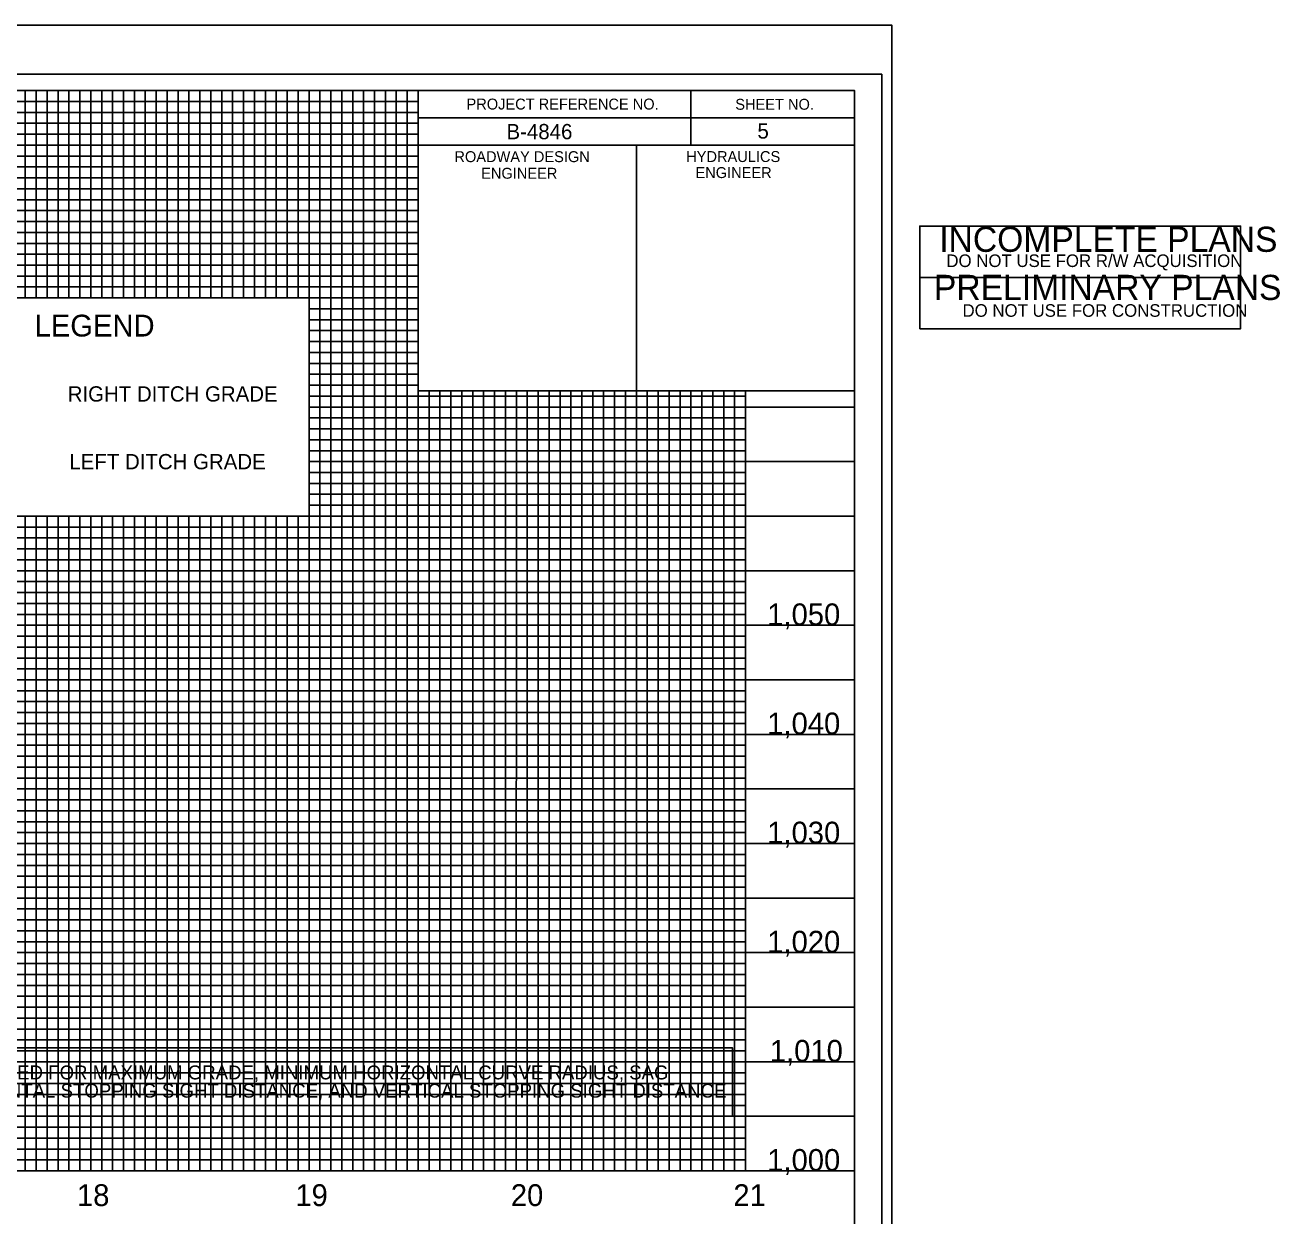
# Model space of a CAD drawing. Extents: x 1427348 to 1429459, y 856278 to 857378.
# Drawn here: x 1428884 to 1429459, y 856832 to 857378 of the extents above; entities that cross this region are included whole.
import ezdxf

# ---------------------------------------------------------------- set-up
doc = ezdxf.new("R2010")
doc.units = 0
for name, color, linetype in [('Exist Vertical Profile Horizontal Axis Label Major', 7, 'Continuous'), ('Exist Vertical Profile Vertical Axis Label', 7, 'Continuous'), ('Prop Grid Mask', 7, 'Continuous'), ('Prop Vertical Profile Curve Label', 7, 'Continuous'), ('Prop Vertical Profile Ditch Grade Left Label', 7, 'Continuous'), ('Prop Vertical Profile Ditch Grade Right Label', 7, 'Continuous'), ('Sheet Cutting Line CELL', 7, 'Continuous'), ('Sheet Data Field CELL', 7, 'Continuous'), ('Sheet DOT Grid CELL', 7, 'Continuous'), ('Sheet Layout Profile Border Port 1', 7, 'Continuous'), ('Sheet Plot Border Inside CELL', 7, 'Continuous'), ('Sheet Plot Border Outside CELL', 7, 'Continuous'), ('Sheet Profile CELL', 7, 'Continuous'), ('Sheet Profile Grid Major CELL', 7, 'Continuous'), ('Sheet Profile Grid Middle CELL', 7, 'Continuous'), ('Sheet Profile Grid Minor CELL', 7, 'Continuous'), ('Sheet Sticker Incomplete CELL', 7, 'Continuous'), ('Sheet Sticker Preliminary CELL', 7, 'Continuous')]:
    doc.layers.add(name, color=color, linetype=linetype)

msp = doc.modelspace()

# ---------------------------------------------------------------- linework, layer by layer
at = {"layer": 'Prop Grid Mask'}
msp.add_lwpolyline([(1428746.32, 856908.99), (1429208.01, 856908.99), (1429208.01, 856877.58), (1428746.32, 856877.58)], close=True, dxfattribs=at)
at = {"layer": 'Sheet Cutting Line CELL'}
msp.add_line((1429280.99, 857377.58), (1427596.99, 857377.58), dxfattribs=at)
at = {"layer": 'Sheet DOT Grid CELL'}
for p, q in [((1428913.99, 857252.58), (1428913.99, 857347.58)), ((1428963.99, 857252.58), (1428963.99, 857347.58)), ((1429013.99, 856852.58), (1429013.99, 857347.58)), ((1429063.94, 857302.58), (1428179.55, 857302.58)), ((1429063.94, 857252.58), (1428388.99, 857252.58)), ((1429063.99, 856852.58), (1429063.99, 857215.03)), ((1429163.99, 856852.58), (1429163.99, 857215.03)), ((1429113.99, 856852.58), (1429113.99, 857210.03)), ((1429213.99, 856852.58), (1429213.99, 857210.03)), ((1429263.99, 857202.58), (1429013.99, 857202.58)), ((1429263.99, 857152.58), (1428179.55, 857152.58)), ((1428913.99, 856852.58), (1428913.99, 857152.58)), ((1428963.99, 856852.58), (1428963.99, 857152.58)), ((1429263.99, 857102.58), (1428179.55, 857102.58)), ((1429263.99, 857052.58), (1428712.85, 857052.58)), ((1429263.99, 857002.58), (1428427.25, 857002.58)), ((1429263.99, 856952.58), (1427763.99, 856952.58)), ((1429263.99, 856902.58), (1427763.99, 856902.58))]:
    msp.add_line(p, q, dxfattribs=at)
at = {"layer": 'Sheet Layout Profile Border Port 1'}
msp.add_lwpolyline([(1427813.99, 857347.58), (1427813.99, 856852.58), (1429213.99, 856852.58), (1429213.99, 857210.03), (1429063.94, 857210.03), (1429063.94, 857347.58)], close=True, dxfattribs=at)
at = {"layer": 'Sheet Plot Border Inside CELL'}
for p, q in [((1429276.49, 857355.13), (1427609.99, 857355.13)), ((1429276.49, 856300.03), (1429276.49, 857355.13))]:
    msp.add_line(p, q, dxfattribs=at)
at = {"layer": 'Sheet Plot Border Outside CELL'}
msp.add_lwpolyline([(1427596.99, 856277.58), (1429280.99, 856277.58), (1429280.99, 857377.58), (1427596.99, 857377.58)], close=True, dxfattribs=at)
at = {"layer": 'Sheet Profile CELL'}
for p, q in [((1429188.99, 857347.53), (1429188.99, 857322.53)), ((1429063.94, 857335.03), (1429263.99, 857335.03)), ((1429163.99, 857322.53), (1429163.99, 857210.08)), ((1427763.99, 856852.58), (1429263.99, 856852.58))]:
    msp.add_line(p, q, dxfattribs=at)
for points in [[(1429263.99, 857347.58), (1427763.99, 857347.58), (1427763.99, 856307.58), (1429263.99, 856307.58)], [(1429063.94, 857347.58), (1429263.99, 857347.58), (1429263.99, 857322.53), (1429063.94, 857322.53)], [(1429063.94, 857322.53), (1429163.99, 857322.53), (1429163.99, 857210.03), (1429063.94, 857210.03)], [(1429163.99, 857322.53), (1429263.99, 857322.53), (1429263.99, 857210.03), (1429163.99, 857210.03)]]:
    msp.add_lwpolyline(points, close=True, dxfattribs=at)
at = {"layer": 'Sheet Profile Grid Major CELL'}
for points in [[(1428863.99, 857252.58), (1428863.99, 857347.58), (1428913.99, 857347.58), (1428913.99, 857252.58)], [(1428963.99, 857252.58), (1428963.99, 857347.58), (1429013.99, 857347.58), (1429013.99, 856852.58), (1429063.99, 856852.58), (1429063.99, 857347.58), (1429090.29, 857347.58)], [(1428179.55, 857302.58), (1429063.99, 857302.58)], [(1429063.99, 857252.58), (1428388.99, 857252.58)], [(1429113.99, 857210.03), (1429113.99, 856852.58), (1429163.99, 856852.58), (1429163.99, 856852.58), (1429163.99, 857215.03)], [(1429213.99, 857210.03), (1429213.99, 856852.58), (1429263.99, 856852.58), (1429263.99, 857202.58)], [(1429013.99, 857202.58), (1429263.99, 857202.58)], [(1429263.99, 857152.58), (1428179.55, 857152.58)], [(1428913.99, 857152.58), (1428913.99, 856852.58), (1428963.99, 856852.58), (1428963.99, 857152.58)], [(1428179.55, 857102.58), (1429263.99, 857102.58)], [(1429263.99, 857052.58), (1428712.85, 857052.58)], [(1428427.25, 857002.58), (1429263.99, 857002.58)], [(1429263.99, 856952.58), (1427763.99, 856952.58), (1427763.99, 856952.58), (1427763.99, 856902.58), (1429263.99, 856902.58)]]:
    msp.add_lwpolyline(points, dxfattribs=at)
at = {"layer": 'Sheet Profile Grid Middle CELL'}
msp.add_line((1427763.99, 857327.58), (1429063.94, 857327.58), dxfattribs=at)
for points in [[(1428888.99, 857252.58), (1428888.99, 857347.58), (1428938.99, 857347.58), (1428938.99, 857252.58)], [(1428988.99, 857252.58), (1428988.99, 857347.58), (1429038.99, 857347.58), (1429038.99, 856852.58), (1429088.99, 856852.58), (1429088.99, 857210.03)], [(1429063.99, 857277.58), (1428388.99, 857277.58)], [(1429013.99, 857227.58), (1429063.99, 857227.58)], [(1429088.99, 857115.38), (1429088.99, 856852.58), (1429138.99, 856852.58), (1429138.99, 857210.03)], [(1429138.99, 857115.38), (1429138.99, 856852.58), (1429188.99, 856852.58), (1429188.99, 857210.03)], [(1429263.99, 857177.58), (1429013.99, 857177.58)], [(1428838.99, 857152.58), (1428838.99, 856852.58), (1428888.99, 856852.58), (1428888.99, 857152.58)], [(1428938.99, 857152.58), (1428938.99, 856852.58), (1428988.99, 856852.58), (1428988.99, 857152.58)], [(1428179.55, 857127.58), (1429088.99, 857127.58)], [(1429088.99, 857127.58), (1429263.99, 857127.58)], [(1429263.99, 857077.58), (1427763.99, 857077.58), (1427763.99, 857027.58), (1428348.9, 857027.58)], [(1428712.85, 857027.58), (1429263.99, 857027.58)], [(1429263.99, 856977.58), (1427763.99, 856977.58), (1427763.99, 856927.58), (1429263.99, 856927.58)], [(1429263.99, 856877.58), (1427763.99, 856877.58)]]:
    msp.add_lwpolyline(points, dxfattribs=at)
at = {"layer": 'Sheet Profile Grid Minor CELL'}
for p, q in [((1429063.99, 857342.58), (1427813.99, 857342.23)), ((1427813.99, 857337.58), (1429063.99, 857337.58)), ((1429063.94, 857217.58), (1429013.99, 857217.58)), ((1429063.94, 857212.58), (1429013.99, 857212.58)), ((1429213.99, 857207.58), (1429013.99, 857207.58)), ((1429013.99, 857197.58), (1429213.99, 857197.58)), ((1429213.99, 857192.58), (1429013.99, 857192.58)), ((1429013.99, 857187.58), (1429213.99, 857187.58)), ((1429213.99, 857167.58), (1429013.99, 857167.58)), ((1429013.99, 857162.58), (1429213.99, 857162.58)), ((1429213.99, 857142.58), (1428179.55, 857142.58)), ((1428179.55, 857137.58), (1429213.99, 857137.58)), ((1429213.99, 857117.58), (1428179.55, 857117.58)), ((1428179.55, 857112.58), (1429213.99, 857112.58)), ((1429213.99, 857107.58), (1428179.55, 857107.58)), ((1428179.55, 857097.58), (1429213.99, 857097.58)), ((1429213.99, 857092.58), (1427813.99, 857092.58)), ((1427813.99, 857087.58), (1429213.99, 857087.58)), ((1429213.99, 857082.58), (1427813.99, 857082.58)), ((1427813.99, 857072.58), (1429213.99, 857072.58)), ((1429213.99, 857067.58), (1428712.85, 857067.58)), ((1428712.85, 857062.58), (1429213.99, 857062.58)), ((1429213.99, 857057.58), (1428712.85, 857057.58)), ((1428712.85, 857047.58), (1429213.99, 857047.58)), ((1429213.99, 857042.58), (1428712.85, 857042.58)), ((1428712.85, 857037.58), (1429213.99, 857037.58)), ((1429213.99, 857032.58), (1428712.85, 857032.58)), ((1428712.85, 857022.58), (1429213.99, 857022.58)), ((1429213.99, 857017.58), (1428712.85, 857017.58)), ((1428712.85, 857012.58), (1429213.99, 857012.58)), ((1429213.99, 857007.58), (1428427.25, 857007.58)), ((1428427.25, 856997.58), (1429213.99, 856997.58)), ((1429213.99, 856992.58), (1428427.25, 856992.58)), ((1427813.99, 856987.58), (1429213.99, 856987.58)), ((1429213.99, 856982.58), (1427813.99, 856982.58)), ((1427813.99, 856972.58), (1429213.99, 856972.58)), ((1429213.99, 856967.58), (1427813.99, 856967.58)), ((1429213.99, 856962.58), (1427813.99, 856962.58)), ((1429213.99, 856957.58), (1427813.99, 856957.58)), ((1427813.99, 856947.58), (1429213.99, 856947.58)), ((1429213.99, 856942.58), (1427813.99, 856942.58)), ((1427813.99, 856937.58), (1429213.99, 856937.58)), ((1429213.99, 856932.58), (1427813.99, 856932.58)), ((1427813.99, 856922.58), (1429213.99, 856922.58)), ((1429213.99, 856917.58), (1427813.99, 856917.58)), ((1427813.99, 856912.58), (1429213.99, 856912.58)), ((1429213.99, 856907.58), (1427813.99, 856907.58)), ((1427813.99, 856897.58), (1429213.99, 856897.58)), ((1429213.99, 856892.58), (1427813.99, 856892.58)), ((1427813.99, 856887.58), (1429213.99, 856887.58)), ((1429213.99, 856882.58), (1427813.99, 856882.58)), ((1427813.99, 856872.58), (1429213.99, 856872.58)), ((1429213.99, 856867.58), (1427813.99, 856867.58)), ((1427813.99, 856862.58), (1429213.99, 856862.58))]:
    msp.add_line(p, q, dxfattribs=at)
for points in [[(1428883.99, 857252.58), (1428883.99, 857347.58), (1428893.99, 857347.58), (1428893.99, 857252.58)], [(1428898.99, 857252.58), (1428898.99, 857347.58), (1428903.99, 857347.58), (1428903.99, 857252.58)], [(1428908.99, 857252.58), (1428908.99, 857347.58), (1428918.99, 857347.58), (1428918.99, 857252.58)], [(1428923.99, 857252.58), (1428923.99, 857347.58), (1428928.99, 857347.58), (1428928.99, 857252.58)], [(1428933.99, 857252.58), (1428933.99, 857347.58), (1428943.99, 857347.58), (1428943.99, 857252.58)], [(1428948.99, 857252.58), (1428948.99, 857347.58), (1428953.99, 857347.58), (1428953.99, 857252.58)], [(1428958.99, 857252.58), (1428958.99, 857347.58), (1428968.99, 857347.58), (1428968.99, 857252.58)], [(1428973.99, 857252.58), (1428973.99, 857347.58), (1428978.99, 857347.58), (1428978.99, 857252.58)], [(1428983.99, 857252.58), (1428983.99, 857347.58), (1428993.99, 857347.58), (1428993.99, 857252.58)], [(1428998.99, 857252.58), (1428998.99, 857347.58), (1429003.99, 857347.58), (1429003.99, 857252.58)], [(1429008.99, 857252.58), (1429008.99, 857347.58), (1429018.99, 857347.58), (1429018.99, 856852.58), (1429023.99, 856852.58), (1429023.99, 857347.58), (1429028.99, 857347.58), (1429028.99, 856852.58), (1429033.99, 856852.58), (1429033.99, 857347.58), (1429043.99, 857347.58), (1429043.99, 856852.58), (1429048.99, 856852.58), (1429048.99, 857347.58), (1429053.99, 857347.58), (1429053.99, 856852.58), (1429058.99, 856852.58), (1429058.99, 857347.58), (1429068.99, 857347.58)], [(1429063.99, 857332.58), (1427813.99, 857332.58), (1427813.99, 857322.58), (1429063.99, 857322.58)], [(1429063.94, 857317.58), (1428179.55, 857317.58)], [(1428179.55, 857312.58), (1429063.99, 857312.58)], [(1429063.99, 857307.58), (1428179.55, 857307.58)], [(1428179.55, 857297.58), (1429063.99, 857297.58)], [(1429063.99, 857292.58), (1428179.55, 857292.58)], [(1428179.55, 857287.58), (1429063.99, 857287.58)], [(1429063.99, 857282.58), (1428388.99, 857282.58)], [(1428388.99, 857272.58), (1429063.99, 857272.58)], [(1429063.99, 857267.58), (1428388.99, 857267.58)], [(1428388.99, 857262.58), (1429063.99, 857262.58)], [(1429063.99, 857257.58), (1428388.99, 857257.58)], [(1429013.99, 857247.58), (1429063.99, 857247.58)], [(1429063.99, 857242.48), (1429013.99, 857242.48)], [(1429013.99, 857237.58), (1429063.99, 857237.58)], [(1429063.99, 857232.58), (1429013.99, 857232.58)], [(1429013.99, 857222.58), (1429063.99, 857222.58)], [(1429068.99, 857210.03), (1429068.99, 856852.58), (1429073.99, 856852.58), (1429073.99, 857210.03)], [(1429078.99, 857210.03), (1429078.99, 856852.58), (1429083.99, 856852.58), (1429083.99, 857210.03)], [(1429093.99, 857210.03), (1429093.99, 856852.58), (1429093.99, 856852.58), (1429098.99, 856852.58), (1429103.99, 856852.58), (1429103.99, 857210.03)], [(1429098.99, 857210.03), (1429098.99, 856852.58)], [(1429108.99, 857210.03), (1429108.89, 856852.63), (1429113.89, 856852.63), (1429118.99, 856852.58), (1429118.99, 857210.03)], [(1429118.99, 857115.38), (1429118.99, 856852.58), (1429123.99, 856852.58), (1429123.99, 857210.03)], [(1429128.99, 857210.03), (1429128.99, 856852.58), (1429133.99, 856852.58), (1429133.99, 857210.03)], [(1429143.99, 857210.03), (1429143.99, 856852.58), (1429148.99, 856852.58), (1429148.99, 857210.03)], [(1429153.99, 857210.03), (1429153.99, 856852.58), (1429158.99, 856852.58), (1429158.99, 857210.03)], [(1429168.99, 857210.03), (1429168.99, 856852.58), (1429173.99, 856852.58), (1429173.99, 857210.03)], [(1429178.99, 857210.03), (1429178.99, 856852.58), (1429183.99, 856852.58), (1429183.99, 857210.03)], [(1429193.99, 857210.03), (1429193.99, 856852.58), (1429198.99, 856852.58), (1429198.99, 857210.03)], [(1429203.99, 857210.03), (1429203.99, 856852.58), (1429208.99, 856852.58), (1429208.99, 857210.03)], [(1429213.99, 857182.58), (1429013.99, 857182.58)], [(1429013.99, 857172.58), (1429213.99, 857172.58)], [(1429213.99, 857157.58), (1429013.99, 857157.58)], [(1428179.55, 857147.58), (1429213.99, 857147.58)], [(1428878.99, 857152.58), (1428878.99, 856852.58), (1428883.99, 856852.58), (1428883.99, 857152.58)], [(1428893.99, 857152.58), (1428893.99, 856852.58), (1428898.99, 856852.58), (1428898.99, 857152.58)], [(1428903.99, 857152.58), (1428903.99, 856852.58), (1428908.99, 856852.58), (1428908.99, 857152.58)], [(1428918.99, 857152.58), (1428918.99, 856852.58), (1428923.99, 856852.58), (1428923.99, 857152.58)], [(1428928.99, 857152.58), (1428928.99, 856852.58), (1428933.99, 856852.58), (1428933.99, 857152.58)], [(1428943.99, 857152.58), (1428943.99, 856852.58), (1428948.99, 856852.58), (1428948.99, 857152.58)], [(1428953.99, 856852.58), (1428958.99, 856852.58), (1428958.99, 857152.58)], [(1428953.99, 857152.58), (1428953.99, 856852.58)], [(1428968.99, 857152.58), (1428968.99, 856852.58), (1428973.99, 856852.58), (1428973.99, 857152.58)], [(1428978.99, 857152.58), (1428978.99, 856852.58), (1428983.99, 856852.58), (1428983.99, 857152.58)], [(1428993.99, 857152.58), (1428993.99, 856852.58), (1428998.99, 856852.58), (1428998.99, 857152.58)], [(1429003.99, 857152.58), (1429003.99, 856852.58), (1429008.99, 856852.58), (1429008.99, 857152.58)], [(1429213.99, 857132.58), (1428179.55, 857132.58)], [(1428179.55, 857122.58), (1429213.99, 857122.58)], [(1429213.99, 856857.58), (1427813.99, 856857.58)]]:
    msp.add_lwpolyline(points, dxfattribs=at)
at = {"layer": 'Sheet Sticker Incomplete CELL'}
msp.add_lwpolyline([(1429293.81, 857261.98), (1429293.81, 857285.48), (1429440.81, 857285.48), (1429440.81, 857261.98)], close=True, dxfattribs=at)
at = {"layer": 'Sheet Sticker Preliminary CELL'}
msp.add_lwpolyline([(1429293.81, 857238.48), (1429293.81, 857261.98), (1429440.81, 857261.98), (1429440.81, 857238.48)], close=True, dxfattribs=at)

# ---------------------------------------------------------------- texts
at = {"layer": 'Exist Vertical Profile Horizontal Axis Label Major'}
for s, p in [('18', (1428907.66, 856836.46)), ('19', (1429007.73, 856836.46)), ('20', (1429106.45, 856836.46)), ('21', (1429208.43, 856836.46))]:
    msp.add_text(s, height=10, dxfattribs=at).set_placement(p)
at = {"layer": 'Exist Vertical Profile Vertical Axis Label'}
for s, p in [('1,050', (1429223.93, 857102.58)), ('1,040', (1429223.93, 857052.58)), ('1,030', (1429223.93, 857002.58)), ('1,020', (1429223.93, 856952.58)), ('1,010', (1429225.12, 856902.58)), ('1,000', (1429223.93, 856852.58))]:
    msp.add_text(s, height=10, dxfattribs=at).set_placement(p)
at = {"layer": 'Prop Vertical Profile Curve Label'}
msp.add_text('LEGEND', height=10, dxfattribs=at).set_placement((1428888.25, 857234.88))
at = {"layer": 'Prop Vertical Profile Ditch Grade Left Label'}
msp.add_text('LEFT DITCH GRADE', height=7, dxfattribs=at).set_placement((1428904.18, 857174.05))
at = {"layer": 'Prop Vertical Profile Ditch Grade Right Label'}
msp.add_text('RIGHT DITCH GRADE', height=7, dxfattribs=at).set_placement((1428903.42, 857205.08))
at = {"layer": 'Sheet Data Field CELL'}
for s, p in [(' B-4846  ', (1429101.88, 857325.27)), (' 5 ', (1429216.85, 857325.57))]:
    msp.add_text(s, height=7, dxfattribs=at).set_placement(p)
for s, p in [('** DESIGN EXCEPTION REQUIRED FOR MAXIMUM GRADE, MINIMUM HORIZONTAL CURVE RADIUS, SAG', (1428751.44, 856894.5)), ('  VERTICAL CURVE K, HORIZONTAL STOPPING SIGHT DISTANCE, AND VERTICAL STOPPING SIGHT DISTANCE', (1428751.44, 856886.14))]:
    msp.add_text(s, height=6.375, rotation=360, dxfattribs=at).set_placement(p)
at = {"layer": 'Sheet Profile CELL'}
for s, height, p in [('PROJECT REFERENCE NO.', 5.0001, (1429086.15, 857338.89)), ('SHEET NO.', 5, (1429209.3, 857338.79)), ('ROADWAY DESIGN', 5.0001, (1429080.6, 857314.79)), ('HYDRAULICS', 5, (1429186.8, 857314.84)), ('ENGINEER', 5, (1429092.85, 857307.19)), ('ENGINEER', 5, (1429191.05, 857307.49))]:
    msp.add_text(s, height=height, dxfattribs=at).set_placement(p)
at = {"layer": 'Sheet Sticker Incomplete CELL'}
for s, height, p in [('INCOMPLETE PLANS', 11.52, (1429302.76, 857273.68)), ('DO NOT USE FOR R/W ACQUISITION', 5.76, (1429306.01, 857266.73))]:
    msp.add_text(s, height=height, dxfattribs=at).set_placement(p)
at = {"layer": 'Sheet Sticker Preliminary CELL'}
for s, height, p in [('PRELIMINARY PLANS', 11.52, (1429300.31, 857251.63)), ('DO NOT USE FOR CONSTRUCTION', 5.76, (1429313.41, 857243.93))]:
    msp.add_text(s, height=height, dxfattribs=at).set_placement(p)

doc.saveas('drawing.dxf')
